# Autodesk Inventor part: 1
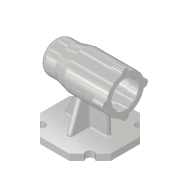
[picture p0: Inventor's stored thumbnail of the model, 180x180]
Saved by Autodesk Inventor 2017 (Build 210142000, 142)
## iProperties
Created: 2019-12
Part Number: 1
Material: 알루미늄 6061-AHC
Document SubType Name: Modeling
Designer: 5-13-le-1
Density: 2.7 g/cm^3
Appearance: 알루미늄 - 짙음
Mass: 725.066 g
Surface Area: 722.161 cm^2
Volume: 268.543 cm^3
Author: 5-13-le-1
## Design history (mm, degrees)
sketch "스케치2"
  geometry: L1 (56, -23.196)-(23.196, -56); L2 (23.196, -56)-(-23.196, -56); L3 (-23.196, -56)-(-56, -23.196); L4 (-56, -23.196)-(-56, 23.196); L5 (-56, 23.196)-(-23.196, 56); L6 (-23.196, 56)-(23.196, 56); L7 (23.196, 56)-(56, 23.196); L8 (56, 23.196)-(56, -23.196); C1 r 56 at (0, 0); 2 further points
  constraints: 16 end point, 2 coincident, 1 centre point, 1 vertical alignment, 17 other
  dimensions: "d0" = 112 diameter of C1; "d1" = 56 distance from line of L2 point (0, 0)
extrude "돌출1" new body sketch "스케치2" distance "d2" = 10; taper "d3" = 0 deg
sketch "스케치3"
  geometry: L1 (0, 0)-(-39.598, -39.598); L2 (0, 0)-(0, -29.306); L3 (0, 0)-(39.598, -39.598); C1 r 7.689 at (-39.598, -39.598); C2 r 6.56 at (39.598, -39.598); A1 r 56 centre (0, 0) between (-39.598, -39.598) and (39.598, -39.598); 1 further point
  constraints: 6 end point, 3 centre point, 2 point on circle, 1 coincident, 1 vertical
  dimensions: "d4" = 112 diameter of A1; "d5" = 45 deg angle of L2 L1; "d6" = 45 deg angle of L2 L3
extrude "돌출2" cut sketch "스케치3" stored distance "d7" = 10; taper "d8" = 0 deg
sketch "스케치4"
  geometry: L1 (-66.415, 80)-(56, 80); L2 (56, 80)-(56, 110); L3 (56, 110)-(-11, 110); L4 (-11, 110)-(-31, 105); L5 (-31, 105)-(-56, 105); L6 (-56, 105)-(-56, 80); L7 (41, 101)-(41, 104); L8 (41, 104)-(-13, 104); L9 (-13, 104)-(-13, 101); L10 (-13, 101)-(-25, 101); L11 (-25, 101)-(-25, 97.5); L12 (-25, 97.5)-(-43, 97.5); L13 (-43, 97.5)-(-43, 94.5); L14 (23.196, 0)-(34.959, 0) reference; L15 (-43, 97.5)-(-43, 96); L16 (-43, 96)-(-47, 96); L17 (-47, 96)-(-47, 90.5); L18 (-47, 90.5)-(-50, 90.5); L19 (-50, 90.5)-(-50, 80); L20 (41, 101)-(56, 101); 2 further points
  constraints: 38 end point, 10 perpendicular, 4 horizontal, 3 point on line, 1 midpoint, 1 parallel, 1 vertical, 1 vertical alignment
  dimensions: "d9" = 112 distance between parallel lines of L2 L6; "d10" = 25 distance of L4.end L5.end; "d11" = 45 distance from line of L3.end L6; "d13" = 54 distance of L7.end L8.end; "d14" = 12 distance of L9.end L10.end; "d15" = 18 distance of L11.end L12.end; "d18" = 60 diameter of L3 L1; "d19" = 80 distance between parallel lines of L14 L1; "d20" = 4 distance of L15.end L16.end; "d21" = 3 distance of L17.end L18.end; "d22" = 50 diameter of L5 L1; "d23" = 42 diameter of L20 L1; "d24" = 48 diameter of L8 L1; "d25" = 42 diameter of L10 L1; "d26" = 35 diameter of L12 L1; "d27" = 32 diameter of L16 L1; "d28" = 21 diameter of L18 L1; "d72" = 15 distance of L7.start L20.end
revolve "회전1" sketch "스케치4" stored, may be unused: angle "d29" = 90 deg
sketch "스케치5"
  geometry: L1 (10.05, -36)-(56.399, -19.13); L2 (10.05, 36)-(56.399, 19.13); L3 (10.05, 36)-(10.05, -36); L4 (10, -31.909)-(10, -45.035) reference; L5 (0, -56)-(10, -56) reference; L6 (0, 56)-(10, 56) reference; L7 (10, 45.035)-(10, 31.909) reference; L8 (56.399, 19.13)-(56.399, 18.521); L9 (56.399, -18.521)-(56.399, -19.13); C1 r 24 at (80, 0) reference; A1 r 30 centre (80, 0) between (56.399, 18.521) and (56.399, -18.521); 3 further points
  constraints: 10 end point, 2 point on circle, 2 vertical, 1 centre point, 1 coincident, 1 parallel
  dimensions: "d30" = 20 distance from line of L5 L1.start; "d31" = 20 distance from line of L2.start L6; "d32" = 110 deg angle of L4 L1; "d33" = 110 deg angle of L7 L2
extrude "돌출3" join sketch "스케치5" stored distance "d34" = 8; taper "d35" = 0 deg
sketch "스케치6"
  geometry: L1 (-45.035, 10)-(-31.909, 10) reference; L2 (-38, 10)-(-17.297, 54.398); L3 (-17.297, 54.398)-(31, 54.398); L4 (31, 54.398)-(31, 10); L5 (33.038, 10)-(44.237, 10) reference; L6 (-38, 10)-(31, 10); L7 (56, 0)-(56, 10) reference; L8 (-56, 0)-(-56, 10) reference; 3 further points
  constraints: 8 end point, 1 horizontal, 1 parallel, 1 perpendicular, 1 point on line
  dimensions: "d36" = 25 distance between parallel lines of L7 L4; "d37" = 18 distance from line of L2.start L8; "d38" = 115 deg angle of L1 L2
extrude "돌출4" join sketch "스케치6" stored distance "d39" = 8; taper "d40" = 0 deg
sketch "스케치7"
  geometry: L1 (0, 0)-(0, 30); C1 r 21 at (0, 0) reference; C2 r 6 at (0, 30); 2 further points
  constraints: 2 end point, 1 centre point, 1 coincident, 1 vertical, 1 vertical alignment, 1 other
  dimensions: "d41" = 12 diameter of C2
extrude "돌출5" join sketch "스케치7" distance "d42" = 16; taper "d43" = 0 deg
sketch "스케치8"
  geometry: A1 r 6 centre (0, 0) between (5.97, -0.6) and (-5.97, -0.6) reference; A2 r 6 centre (-30, -30) between (-29.4, -24.03) and (-29.4, -35.97) reference; A3 r 6 centre (0, -60) between (-5.97, -59.4) and (5.97, -59.4) reference; A4 r 6 centre (30, -30) between (29.4, -35.97) and (29.4, -24.03) reference; 5 further points
  constraints: 4 coincident
hole "구멍1" sketch "스케치8" at (0, 0), (-30, -30), (0, -60), (30, -30) diameter "d47" = 3.242; stored, may be unused: countersink angle "d51" = 90 deg, drill point angle "d53" = 118 deg; dims "d48" = 8, "d49" = 4, "d50" = 2, "d52" = 11
node "작업 평면1"
sketch "스케치9"
  geometry: L1 (-20.5, 80)-(20.5, 80); L2 (-56, 55)-(-56, 105) reference; L3 (56, 86)-(56, 74) reference; 3 further points
  constraints: 2 end point, 2 horizontal
  dimensions: "d55" = 35.5 distance from line of L1.start L2; "d56" = 35.5 distance from line of L3 L1.end
feature "엠보싱1" sketch "스케치9" dims "d0" = 112, "d1" = 56, "d57" = 0.5, "d58" = 0
fillet "모깎기1" dims "d59" = 10
chamfer "모따기1" distance "d61" = 1; stored, may be unused: second distance "d62" = 2, angle "d63" = 45 deg
fillet "모깎기3" dims "d64" = 3
fillet "모깎기4" dims "d65" = 3
fillet "모깎기5" dims "d66" = 0.3
fillet "모깎기6" dims "d67" = 3
fillet "모깎기7" dims "d68" = 3
fillet "모깎기8" dims "d69" = 3
node "솔리드1"
mirror "미러1"
pattern_circular "원형 패턴1" dims angle "d45" = 360 deg
